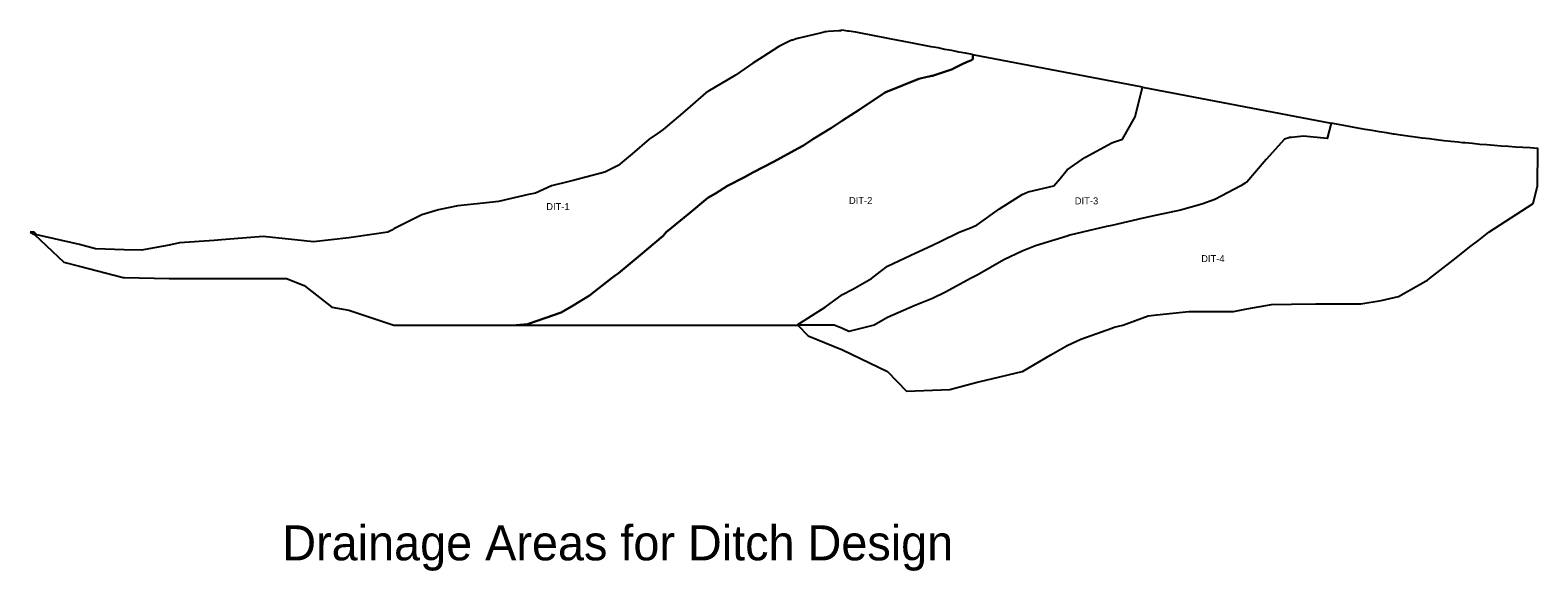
# Model space of a CAD drawing. Extents: x 2812 to 3890, y 2690 to 3077.
import ezdxf

# ---------------------------------------------------------------- set-up
doc = ezdxf.new("R2010")
doc.units = 0
doc.layers.add('SURVEY - DRAINAGE - Area Shapes', color=7, linetype='Continuous')
doc.layers.add('SURVEY - DRAINAGE - Area Shapes Text', color=7, linetype='Continuous')

msp = doc.modelspace()

# ---------------------------------------------------------------- linework, layer by layer
at = {"layer": 'SURVEY - DRAINAGE - Area Shapes'}
for q in [(3485.8, 3059.2), (3741.8, 3010.2)]:
    msp.add_line((3607.1, 3036), q, dxfattribs=at)
for points in [[(3359.6, 3070.5), (3358.3, 3070.1), (3357.1, 3069.7), (3356.5, 3069.5), (3356, 3069.3), (3355.2, 3069), (3347.2, 3065.1), (3335.8, 3057.6), (3328.6, 3053.1), (3316.3, 3044.6), (3296.5, 3032.9), (3296, 3032.5), (3295.1, 3031.9), (3278.3, 3017.5), (3264.5, 3005.8), (3260.5, 3002.8), (3254.5, 2998.7), (3242.3, 2988.4), (3232.4, 2980), (3222.9, 2975.3), (3200.3, 2969.2), (3197.3, 2968.6), (3184.7, 2965.5), (3173.3, 2960.3), (3168.2, 2959.3), (3147, 2954.3), (3136.2, 2953.1), (3117.9, 2951.2), (3104.1, 2948.4), (3092, 2944.8), (3072, 2934.6), (3070.6, 2933.8), (3067.8, 2932.3), (3043.3, 2928.8), (3039.9, 2928.2), (3014.6, 2925.4), (3007.9, 2926.1), (2978.8, 2929.2), (2975.8, 2928.9), (2949, 2926.8), (2943.7, 2926.4), (2919, 2924.7), (2911.6, 2923), (2891.9, 2919.5), (2879.5, 2919.8), (2859, 2920.4), (2847.5, 2923.4), (2817.1, 2930.5), (2815.4, 2932.2), (2815.1, 2932.3), (2814.3, 2932.3)], [(3485.8, 3059.2), (3485.6, 3059.3), (3480.6, 3060.2), (3475.7, 3061.1), (3470.8, 3062.1), (3465.9, 3063), (3461, 3064), (3456.1, 3064.9), (3451.2, 3065.8), (3446.3, 3066.8), (3441.4, 3067.7), (3436.4, 3068.7), (3431.5, 3069.6), (3426.6, 3070.5), (3421.7, 3071.5), (3416.8, 3072.4), (3411.9, 3073.4), (3407, 3074.3), (3402.1, 3075.2), (3397.1, 3076), (3396.5, 3076), (3392.2, 3076.8), (3391.9, 3076.6), (3391.7, 3076.6), (3391.5, 3076.4), (3391.4, 3076.4), (3391.4, 3076.4), (3391.4, 3076.4), (3391.4, 3076.4), (3391.3, 3076.3), (3391.3, 3076.3), (3390, 3076.2), (3382.5, 3075.7), (3381, 3075.6), (3380.2, 3075.5), (3378.6, 3075.1), (3376.7, 3074.7), (3363.6, 3071.6), (3361.5, 3071.1), (3361.4, 3071.1), (3360.7, 3070.9), (3359.6, 3070.5)], [(3104.1, 2865.9), (3136.2, 2865.9), (3159.4, 2865.9), (3167.6, 2866.6), (3168.2, 2866.8), (3191.6, 2874.9), (3200.3, 2879.8), (3211.9, 2887.1), (3227.4, 2899.1), (3230.3, 2901.3), (3232.4, 2902.7), (3248.2, 2915.9), (3264.5, 2929.8), (3265.7, 2931.1), (3266.8, 2932.3), (3283.4, 2946), (3296.5, 2956.8), (3301.9, 2959.9), (3310.5, 2965.5), (3322.6, 2971.7), (3328.6, 2975.1), (3343.9, 2982.9), (3360.7, 2992.1), (3364.9, 2994.3), (3371.4, 2998.7), (3384.8, 3007), (3392.8, 3012.1), (3404.5, 3019.8), (3422.8, 3031.9), (3424.1, 3032.7), (3424.9, 3033), (3447.2, 3041.9), (3453.1, 3043.3), (3454.7, 3043.7), (3456.4, 3044.1), (3456.9, 3044.2), (3471.2, 3048.8), (3472.1, 3049.3), (3475.9, 3051.2), (3478.3, 3052.4)], [(3478.3, 3052.4), (3475.9, 3051.2), (3472.1, 3049.3), (3471.2, 3048.8), (3456.9, 3044.2), (3456.4, 3044.1), (3454.7, 3043.7), (3453.1, 3043.3), (3447.2, 3041.9), (3424.9, 3033), (3424.1, 3032.7), (3422.8, 3031.9), (3404.5, 3019.8), (3392.8, 3012.1), (3384.8, 3007), (3371.4, 2998.7), (3364.9, 2994.3), (3360.7, 2992.1), (3343.9, 2982.9), (3328.6, 2975.1), (3322.6, 2971.7), (3310.5, 2965.5), (3301.9, 2959.9), (3296.5, 2956.8), (3283.4, 2946), (3266.8, 2932.3), (3265.7, 2931.1), (3264.5, 2929.8), (3248.2, 2915.9), (3232.4, 2902.7), (3230.3, 2901.3), (3227.4, 2899.1), (3211.9, 2887.1), (3200.3, 2879.8), (3191.6, 2874.9), (3168.2, 2866.8), (3167.6, 2866.6), (3159.4, 2865.9)], [(3485.8, 3059.2), (3485.9, 3056.1), (3484.9, 3055.3), (3481.2, 3053.9), (3478.3, 3052.4)], [(3478.3, 3052.4), (3481.2, 3053.9), (3484.9, 3055.3), (3485.9, 3056.1), (3485.8, 3059.2)], [(3360.5, 2865.9), (3360.6, 2866.1), (3360.7, 2866.2), (3380.4, 2878.8), (3392.8, 2887.7), (3400, 2891.6), (3413.4, 2899.1), (3419.9, 2904.2), (3424.9, 2907.9), (3441, 2915.6), (3456.9, 2923), (3463, 2926), (3476, 2932.3), (3485.4, 2936), (3489, 2937.5), (3504.8, 2949.1), (3521.1, 2959.3), (3525.4, 2961.1), (3543.7, 2965.5), (3548.2, 2970.7), (3553.2, 2977), (3565.8, 2985.7), (3585.2, 2996.3), (3587, 2996.9), (3592.7, 2998.7), (3601.7, 3014.8), (3607.1, 3036)], [(3360.5, 2865.9), (3360.6, 2866.1), (3360.7, 2866.2), (3380.4, 2878.8), (3392.8, 2887.7), (3400, 2891.6), (3413.4, 2899.1), (3419.9, 2904.2), (3424.9, 2907.9), (3441, 2915.6), (3456.9, 2923), (3463, 2926), (3476, 2932.3), (3485.4, 2936), (3489, 2937.5), (3504.8, 2949.1), (3521.1, 2959.3), (3525.4, 2961.1), (3543.7, 2965.5), (3548.2, 2970.7), (3553.2, 2977), (3565.8, 2985.7), (3585.2, 2996.3), (3587, 2996.9), (3592.7, 2998.7), (3601.7, 3014.8), (3607.1, 3036)], [(3741.8, 3010.2), (3739, 2999.4), (3722.2, 3001), (3713.5, 3000.1), (3713.2, 3000.1), (3713.1, 3000.1), (3712.7, 3000), (3712.3, 3000), (3712.3, 3000), (3712.1, 2999.9), (3712.1, 2999.9), (3711.9, 2999.9), (3711.7, 2999.8), (3708.6, 2998.7), (3695.4, 2984.3), (3681.5, 2968.1), (3679.9, 2967.1), (3677.4, 2965.5), (3658.8, 2955.7), (3649.4, 2952.4), (3634.2, 2948), (3617.3, 2944.5), (3607.6, 2942.4), (3585.2, 2937.2), (3581.4, 2936.3), (3564.1, 2932.3), (3555.2, 2930.2), (3553.2, 2929.5), (3530.6, 2922.5), (3521.1, 2918.8), (3508, 2912.6), (3489, 2901.5), (3487.4, 2900.8), (3484.1, 2899.1), (3466.2, 2889.5), (3456.9, 2885), (3443.8, 2879.6), (3424.9, 2871.3), (3421.5, 2869.4), (3415.2, 2865.9), (3397.3, 2861.3), (3392.8, 2863.4), (3386.7, 2865.9), (3360.5, 2865.9)], [(3741.8, 3010.2), (3739, 2999.4), (3722.2, 3001), (3713.5, 3000.1), (3713.2, 3000.1), (3713.1, 3000.1), (3712.7, 3000), (3712.3, 3000), (3712.3, 3000), (3712.1, 2999.9), (3712.1, 2999.9), (3711.9, 2999.9), (3711.7, 2999.8), (3708.6, 2998.7), (3695.4, 2984.3), (3681.5, 2968.1), (3679.9, 2967.1), (3677.4, 2965.5), (3658.8, 2955.7), (3649.4, 2952.4), (3634.2, 2948), (3617.3, 2944.5), (3607.6, 2942.4), (3585.2, 2937.2), (3581.4, 2936.3), (3564.1, 2932.3), (3555.2, 2930.2), (3553.2, 2929.5), (3530.6, 2922.5), (3521.1, 2918.8), (3508, 2912.6), (3489, 2901.5), (3487.4, 2900.8), (3484.1, 2899.1), (3466.2, 2889.5), (3456.9, 2885), (3443.8, 2879.6), (3424.9, 2871.3), (3421.5, 2869.4), (3415.2, 2865.9), (3397.3, 2861.3), (3392.8, 2863.4), (3386.7, 2865.9), (3360.7, 2865.9)], [(3889.2, 2966.8), (3889.2, 2966.8), (3889.5, 2989.9), (3889.6, 2992.2), (3889.2, 2992.2), (3884, 2992.5), (3878.8, 2992.8), (3873.7, 2993.1), (3868.5, 2993.5), (3863.4, 2993.8), (3858.3, 2994.2), (3853.1, 2994.7), (3848, 2995.1), (3842.8, 2995.6), (3837.7, 2996.1), (3835.6, 2996.3), (3832.6, 2996.6), (3827.4, 2997.2), (3822.3, 2997.7), (3817.2, 2998.3), (3812.1, 2999), (3806.9, 2999.6), (3801.8, 3000.3), (3796.7, 3001), (3791.6, 3001.7), (3786.8, 3002.5), (3786.5, 3002.5), (3781.4, 3003.3), (3776.3, 3004.1), (3771.2, 3004.9), (3766.1, 3005.8), (3761, 3006.7), (3756, 3007.6), (3750.9, 3008.5), (3745.8, 3009.5), (3741.8, 3010.2)], [(3886.2, 2952.8), (3889.2, 2965.5), (3889.2, 2966.2), (3889.2, 2966.7), (3889.2, 2966.7)], [(3889.2, 2966.7), (3889.2, 2966.8)], [(3889.2, 2966.8), (3889.2, 2966.8)], [(3889.2, 2966.7), (3889.2, 2966.7), (3889.2, 2966.7)], [(3360.7, 2865.9), (3368.1, 2858.2), (3392.8, 2848.1), (3424.9, 2832.8), (3438.4, 2818.7), (3456.9, 2819.3), (3469.5, 2819.8), (3489, 2825), (3495, 2826.6), (3521.1, 2832.7), (3521.1, 2832.7), (3521.3, 2832.8), (3541.6, 2844.7), (3553.2, 2851.3), (3562.9, 2855.9), (3585.2, 2863.8), (3586.8, 2864.3), (3592.9, 2865.9), (3611, 2872.4), (3617.3, 2873.2), (3640.1, 2875.5), (3649.4, 2875.5), (3672.1, 2875.6), (3681.5, 2877.6), (3699.2, 2880.7), (3713.5, 2880.9), (3730.9, 2881.1), (3745.6, 2881.1), (3763, 2881.1), (3777.7, 2883.4), (3790.1, 2886.3), (3809.8, 2897.5), (3810.7, 2898.1), (3812.2, 2899.1), (3829, 2912.4), (3841.9, 2922.5), (3847.4, 2926.5), (3854.5, 2932.3), (3886.2, 2952.8)], [(2814.3, 2932.3), (2812.2, 2932.3)], [(2812.2, 2932.3), (2815.4, 2930.6), (2836.2, 2910.8)], [(2836.2, 2910.8), (2847.5, 2908.1)], [(2847.5, 2908.1), (2878.7, 2900)], [(2878.7, 2900), (2879.5, 2900), (2911.6, 2899.1), (2943.7, 2899.1)], [(2943.7, 2899.1), (2975.8, 2899.1), (2995.3, 2899.1), (3007.9, 2894.2), (3027.7, 2878.6)], [(3027.7, 2878.6), (3039.9, 2876.6)], [(3039.9, 2876.6), (3072, 2865.9)], [(3072, 2865.9), (3104.1, 2865.9)], [(3159.4, 2865.9), (3168.2, 2865.9), (3200.3, 2865.9), (3232.4, 2865.9), (3264.5, 2865.9), (3296.5, 2865.9), (3328.6, 2865.9), (3360.5, 2865.9)]]:
    msp.add_lwpolyline(points, dxfattribs=at)

# ---------------------------------------------------------------- texts
at = {"layer": 'SURVEY - DRAINAGE - Area Shapes Text'}
for s, height, p in [('DIT-1', 5, (3181, 2948.1)), ('DIT-2', 5, (3397.3, 2952.5)), ('DIT-3', 5, (3558.7, 2952.2)), ('DIT-4', 5, (3649, 2910.9)), ('Drainage Areas for Ditch Design', 25, (2992.4, 2697.7))]:
    msp.add_text(s, height=height, dxfattribs=at).set_placement(p)

doc.saveas('drawing.dxf')
